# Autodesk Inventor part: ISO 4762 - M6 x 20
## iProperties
Created: 2008-08
Part Number: ISO 4762 - M6 x 20
Material: BgAAAEgAAABOAEEATQBFAFMACgBNAGEAdABlAHIAaQBhAGwAcwAKADEAOgBTAHQAZQBlAGwALAAgAE0AaQBsAGQACgAKAEUATgBEAAoAAAA=
Description: Innensechskantschraube
Vendor: Autodesk Inc.
Document SubType Name: Modeling
Standard: ISO 4762
Designer: U.Rapp
Standards Organization: DIN
Language: de-DE
Size Designation: M6 x 20
Categories: <MemberInstance Version="R10.0.0"><Categories><Category DisplayName="Schrauben" InternalName="e4da775c-781d-43d5-af7c-5136215cf5a6" Mnemonic="FSTN"><Category Di
Author: U.Rapp
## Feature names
1. Körper [Revolution]
2. Loch [Extrusion]
3. Rundung1 [Fillet]
4. Fase1 [Chamfer]
